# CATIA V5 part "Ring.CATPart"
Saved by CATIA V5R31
Part number: Part1.1
Bounding box of the stored display mesh (mm): x -5 to 5, y -15 to 15, z -15 to 15
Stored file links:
  D:\PROJECTS\Project 2021\US EDITION\CATIA V5 6R 2021\Resources\Part Files\c12_catia_v5_6r2021_prt\c12_catia_v5-6r2021 figr_12-12\Ring.CATPart
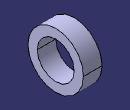
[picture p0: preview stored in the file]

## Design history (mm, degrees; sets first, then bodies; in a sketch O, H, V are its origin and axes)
Body1 (main body)
  Sketch1 on yz-plane, origin (0, 0, 0), H (0, 1, 0), V (0, 0, 1)
    circle A1 centre (0, 0) radius 15
    circle A2 centre (0, 0) radius 10
    radius A1 = 15
    radius A2 = 10
  Pad1: profile Sketch1, direction (1, 0, 0), length 5, mirrored extent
